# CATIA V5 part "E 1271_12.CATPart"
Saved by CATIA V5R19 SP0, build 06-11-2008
Nomenclature: E 1271_12
Description: PART-E 1271_12-DESC
Property "Hersteller": "Meusburger"
Property "Bestellnummer": "E 1271/12"
Property "Teilenummer": "E 1271/12"
Property "Beschreibung": "Ringschraube drehbar _ Revolvable eye bolt"
Material "Steel": density 7860 kg/m3, Young's modulus 2e+11 Pa, Poisson ratio 0.266, thermal expansion 1.17e-05 1/K
Bounding box of the stored display mesh (mm): x -15 to 15, y -28 to 28, z -18 to 55
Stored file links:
  G:\UTB\Kombinované\Bakalářská práce\Catia\FORMA\E 1271_12.CATPart
  D:\Aplikace\CATIA\Nová složka\win_b64\startup\materials\Catalog.CATMaterial
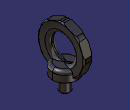
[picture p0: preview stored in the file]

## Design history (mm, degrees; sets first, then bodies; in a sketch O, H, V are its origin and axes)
Body1 "E 1271_12" (main body)
  Solid1: solid without history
